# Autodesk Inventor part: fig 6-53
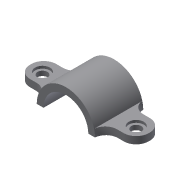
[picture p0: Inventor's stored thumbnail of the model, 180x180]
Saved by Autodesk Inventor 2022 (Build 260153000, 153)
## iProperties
Created: 2004-05
Part Number: fig 6-53
Document SubType Name: Modeling
Designer: CADCIM Technologies
Manufacturer: Standard
Standards Organization: Custom
Density: 1 g/cm^3
Material: Generic
Appearance: Default
Author: CADCIM Technologies
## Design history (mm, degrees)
node "Sketch1"
sketch "Sketch2"
  geometry: L1 (23.378, 0)-(17.996, 0); L2 (-17.996, 0)-(-23.378, 0); A1 r 23.378 centre (0, 0) between (23.378, 0) and (-23.378, 0); A2 r 17.996 centre (0, 0) between (17.996, 0) and (-17.996, 0)
  constraints: 4 end point, 4 point on circle, 2 centre point, 1 collinear, 1 horizontal
extrude "Extrusion1" new body sketch "Sketch2" stored distance "d0" = 38.75; taper "d1" = 0 deg
sketch "Sketch3"
  geometry: L1 (23.378, 0)-(17.996, 0); L2 (-17.996, 0)-(-23.378, 0) reference; L3 (-23.378, 0)-(-47.662, 0); L4 (-47.662, 0)-(-47.662, 5.722); L5 (-47.662, 5.722)-(-22.667, 5.722); A1 r 17.996 centre (0, 0) between (17.996, 0) and (-17.996, 0) reference; A2 r 23.378 centre (0, 0) between (23.378, 0) and (-23.378, 0) reference; 1 further point
  constraints: 10 end point, 5 point on circle, 2 centre point, 1 collinear, 1 horizontal, 1 midpoint, 1 parallel, 1 perpendicular, 3 other
extrude "Extrusion2" join sketch "Sketch3" stored distance "d2" = 21; taper "d3" = 0 deg
fillet "Fillet1" dims "d4" = 10
hole "Hole1" diameter "d7" = 8; stored, may be unused: countersink angle "d11" = 90 deg, drill point angle "d13" = 118 deg; dims "d5" = 10, "d6" = 10, "d8" = 6, "d9" = 12, "d10" = 2, "d12" = 12
fillet "Fillet2" dims "d14" = 9.5
mirror "Mirror1"
body "Solid1"
